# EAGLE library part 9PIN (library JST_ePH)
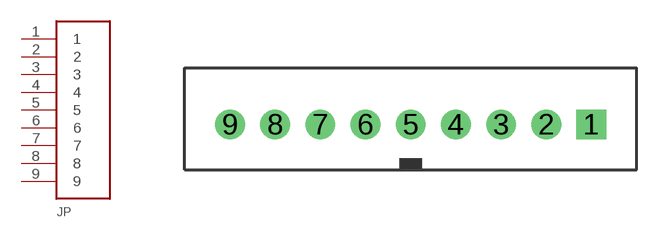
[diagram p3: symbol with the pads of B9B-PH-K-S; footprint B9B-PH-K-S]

Designator prefix JP

## 9PIN  [B9B-PH-K-S]
1  1
2  2
3  3
4  4
5  5
6  6
7  7
8  8
9  9

## Footprint B9B-PH-K-S (pad centres in mm)
drill 0.813 square: 1 8,0
drill 0.813 round: 2 6,0; 3 4,0; 4 2,0; 5 0,0; 6 -2,0; 7 -4,0; 8 -6,0; 9 -8,0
